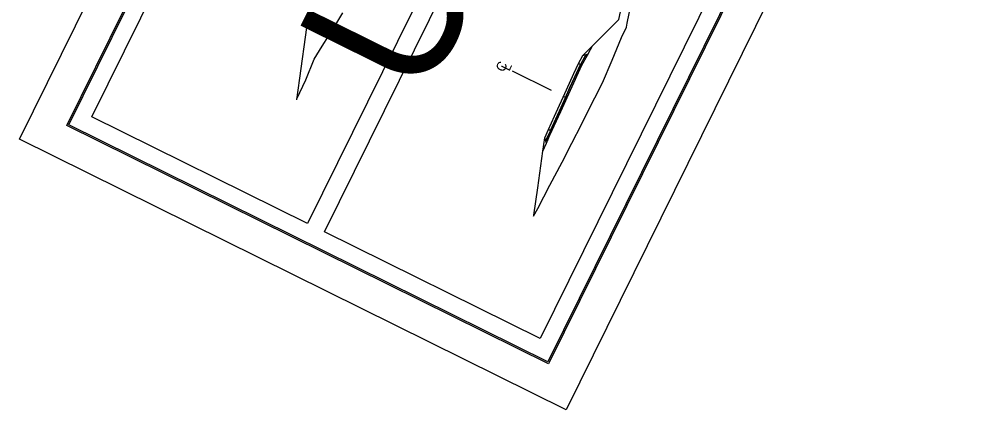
# Model space of a CAD drawing. Extents: x 14090526 to 14125274, y 8637242 to 8677144.
# Drawn here: x 14118796 to 14120076, y 8671493 to 8672010 of the extents above; entities that cross this region are included whole.
import ezdxf

# ---------------------------------------------------------------- set-up
doc = ezdxf.new("R2010")
doc.units = 0
for name, color, linetype in [('dsnNonPlotable', 7, 'Continuous'), ('dsnShadingGranular', 7, 'Continuous'), ('dsnShadingPaved', 7, 'Continuous'), ('dsnTextOverlapEven', 7, 'Continuous'), ('Level 1', 7, 'Continuous'), ('TC_Grading', 7, 'Continuous'), ('TC_PCCPavement', 7, 'Continuous'), ('TC_ShoulderEarthFill', 7, 'Continuous'), ('TC_ShoulderGranular', 7, 'Continuous'), ('TC_Subbase', 7, 'Continuous'), ('Terrain', 7, 'Continuous')]:
    doc.layers.add(name, color=color, linetype=linetype)

msp = doc.modelspace()

# ---------------------------------------------------------------- linework, layer by layer
at = {"layer": 'dsnNonPlotable'}
for points in [[(14118795.9, 8671851.1), (14119351.6, 8672975.2), (14120075.9, 8672617.1), (14119520.2, 8671493)], [(14118861.3, 8671870.1), (14119378, 8672915.3), (14120012.8, 8672601.5), (14119496, 8671556.3)]]:
    msp.add_lwpolyline(points, close=True, dxfattribs=at)
at = {"layer": 'dsnShadingGranular'}
for points in [[(14119536.6, 8671951.3), (14119542.4, 8671961.9), (14119546.6, 8671963.3), (14119539.3, 8671950)], [(14119491.8, 8671853), (14119496.7, 8671864), (14119499.4, 8671862.6), (14119493.1, 8671849)]]:
    msp.add_lwpolyline(points, close=True, dxfattribs=at)
at = {"layer": 'dsnShadingPaved'}
msp.add_lwpolyline([(14119496.7, 8671864), (14119504.8, 8671881.8), (14119520.6, 8671916.4), (14119530.6, 8671938.2), (14119536.6, 8671951.3), (14119539.3, 8671950), (14119531.4, 8671932.6), (14119525.3, 8671919.4), (14119519.3, 8671906.3), (14119513.4, 8671893.4), (14119499.4, 8671862.6)], close=True, dxfattribs=at)
at = {"layer": 'dsnTextOverlapEven'}
msp.add_line((14119500.9, 8671915.5), (14119449.1, 8671941), dxfattribs=at)
for points in [[(14118892.1, 8671880.5), (14119388.5, 8672884.5), (14119674, 8672743.3), (14119177.6, 8671739.3)], [(14119200, 8671728.3), (14119696.4, 8672732.2), (14119982, 8672591.1), (14119485.6, 8671587.1)]]:
    msp.add_lwpolyline(points, close=True, dxfattribs=at)
at = {"layer": 'Level 1'}
msp.add_lwpolyline([(14118858.6, 8671869.2), (14119377.1, 8672918), (14120015.5, 8672602.4), (14119496.9, 8671553.6)], close=True, dxfattribs=at)
at = {"layer": 'TC_Grading'}
msp.add_line((14119542.4, 8671961.9), (14119589.9, 8672009.8), dxfattribs=at)
for points in [[(14119589.9, 8672009.8), (14119595.7, 8672036.6), (14119602.6, 8672068.2), (14119606.4, 8672085.7), (14119612, 8672100.7)], [(14119477.6, 8671750.5), (14119482.6, 8671786.5), (14119489.3, 8671835.2), (14119491.8, 8671853)]]:
    msp.add_lwpolyline(points, dxfattribs=at)
at = {"layer": 'TC_PCCPavement'}
msp.add_line((14119519.3, 8671906.3), (14119516.6, 8671907.6), dxfattribs=at)
for points in [[(14119496.7, 8671864), (14119504.8, 8671881.8), (14119520.6, 8671916.4), (14119530.6, 8671938.2), (14119536.6, 8671951.3)], [(14119496.7, 8671864), (14119499.4, 8671862.6), (14119513.4, 8671893.4), (14119519.3, 8671906.3), (14119525.3, 8671919.4), (14119531.4, 8671932.6), (14119539.3, 8671950), (14119536.6, 8671951.3)]]:
    msp.add_lwpolyline(points, dxfattribs=at)
at = {"layer": 'TC_ShoulderEarthFill'}
for p, q in [((14119549.4, 8671964.2), (14119555, 8671974.6)), ((14119489.3, 8671835.2), (14119494.1, 8671846))]:
    msp.add_line(p, q, dxfattribs=at)
at = {"layer": 'TC_ShoulderGranular'}
msp.add_lwpolyline([(14119536.6, 8671951.3), (14119542.4, 8671961.9), (14119549.4, 8671964.2), (14119548.3, 8671962.2), (14119545.1, 8671960.5), (14119539.3, 8671950)], close=True, dxfattribs=at)
msp.add_lwpolyline([(14119494.1, 8671846), (14119491.8, 8671853), (14119496.7, 8671864), (14119499.4, 8671862.6), (14119494.4, 8671851.7), (14119495.4, 8671848.8)], dxfattribs=at)
at = {"layer": 'TC_Subbase'}
msp.add_lwpolyline([(14119494.1, 8671846), (14119498.8, 8671856.4), (14119513, 8671887.7), (14119541.1, 8671949.1), (14119548.3, 8671962.2)], dxfattribs=at)
at = {"layer": 'Terrain'}
msp.add_line((14119180.3, 8672027.7), (14119162.9, 8671903.1), dxfattribs=at)
for points in [[(14119477, 8671749.4), (14119482.5, 8671759.5), (14119498.8, 8671790.2), (14119515, 8671820.9), (14119527.7, 8671845.8), (14119540.5, 8671870.7), (14119548.1, 8671886.1), (14119568.3, 8671925.8), (14119581, 8671955.7), (14119593.7, 8671985.7), (14119600.2, 8671999.6), (14119601.2, 8672004.6), (14119606.5, 8672030.4)], [(14119163.6, 8671904.4), (14119175.5, 8671929.7), (14119186.5, 8671957.2), (14119197, 8671974.4), (14119213.9, 8672000.6), (14119224.6, 8672018.6)]]:
    msp.add_lwpolyline(points, dxfattribs=at)

# ---------------------------------------------------------------- texts
at = {"layer": 'dsnTextOverlapEven'}
for s, p in [('C', (14119437.6, 8671939)), ('L', (14119444.8, 8671940.4))]:
    msp.add_text(s, height=12.8, rotation=63.6911, dxfattribs=at).set_placement(p)
at = {"layer": 'TC_PCCPavement'}
msp.add_text('US 75', height=192, rotation=63.6912, dxfattribs=at).set_placement((14119331.7, 8671898.6))

doc.saveas('drawing.dxf')
